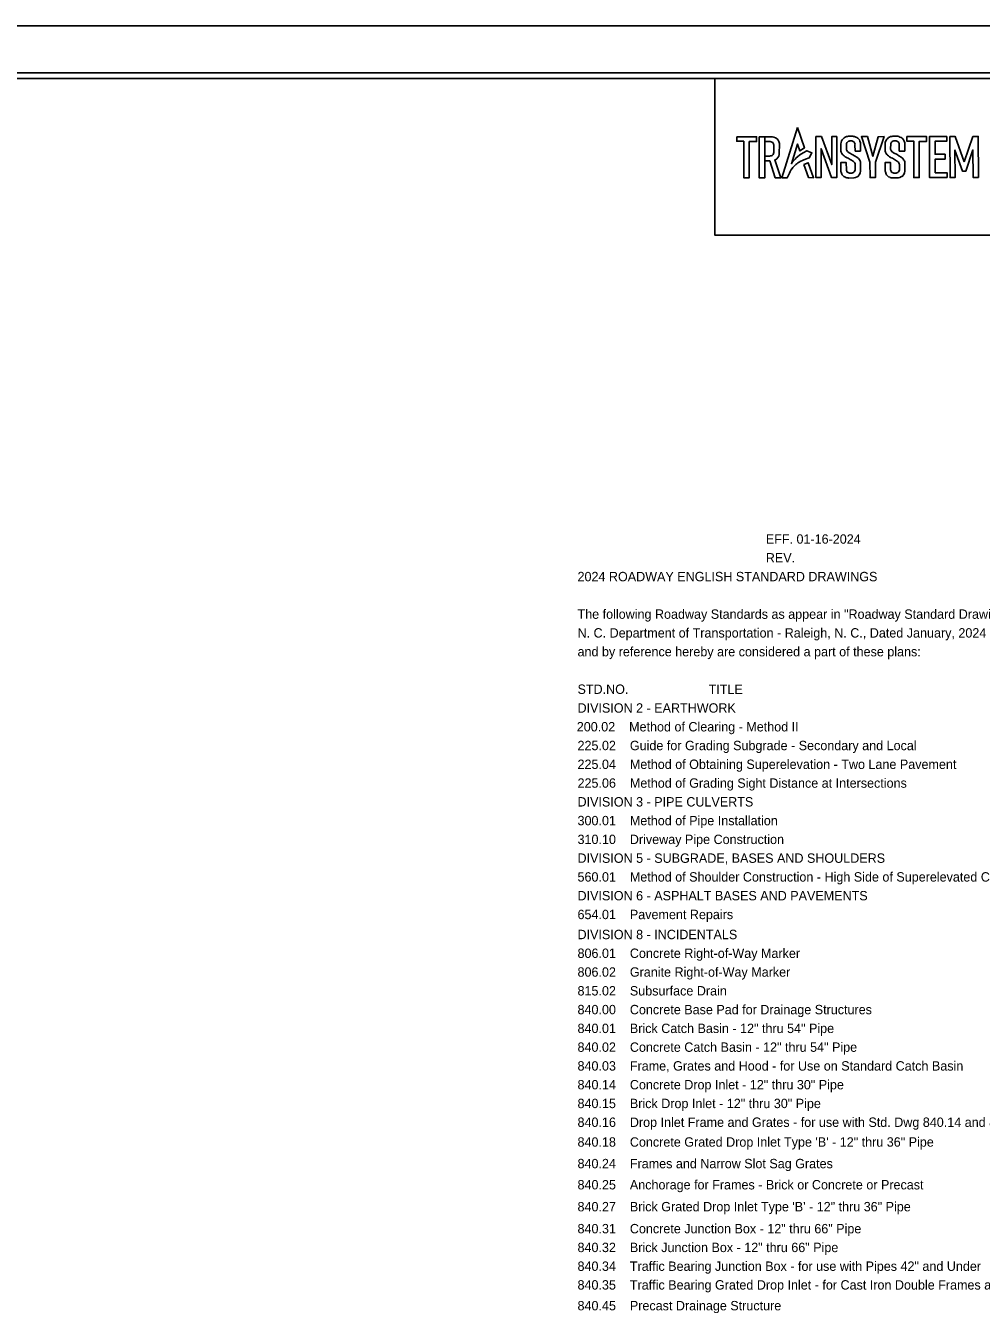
# Model space of a CAD drawing. Extents: x 1537922 to 1539606, y 409903 to 410998.
# Drawn here: x 1538895 to 1539302, y 410448 to 410998 of the extents above; entities that cross this region are included whole.
import ezdxf

# ---------------------------------------------------------------- set-up
doc = ezdxf.new("R2010")
doc.units = 0
for name, color, linetype in [('Default', 7, 'Continuous'), ('Old_Level_58', 7, 'Continuous'), ('Sheet Cutting Line CELL', 7, 'Continuous'), ('Sheet Plan CELL', 7, 'Continuous'), ('Sheet Plot Border Inside CELL', 7, 'Continuous'), ('Sheet Plot Border Outside CELL', 7, 'Continuous')]:
    doc.layers.add(name, color=color, linetype=linetype)

msp = doc.modelspace()

# ---------------------------------------------------------------- linework, layer by layer
at = {"layer": 'Default'}
for points in [[(1539224.12, 410954.94), (1539217.45, 410933.6), (1539219.67, 410933.61), (1539220.02, 410934.45), (1539220.59, 410935.61), (1539220.9, 410936.24), (1539221.28, 410936.78), (1539221.8, 410937.54), (1539222.13, 410938.01), (1539222.51, 410938.4), (1539222.89, 410938.79), (1539223.37, 410939.29), (1539223.78, 410939.56), (1539224.2, 410939.89), (1539224.76, 410940.21), (1539225.25, 410940.49), (1539226.47, 410941.06), (1539227.47, 410941.47), (1539229.11, 410942.03), (1539230.24, 410944.17), (1539228.07, 410945.13), (1539226.44, 410944.24), (1539225.06, 410943.34), (1539224.08, 410942.54), (1539223.55, 410942.11), (1539223.02, 410941.55), (1539222.49, 410940.98), (1539222.09, 410940.56), (1539221.71, 410939.91), (1539221.5, 410939.55), (1539224.13, 410947.93), (1539225.13, 410945.04), (1539227.03, 410946.29)], [(1539198.15, 410951.09), (1539206.62, 410951.1), (1539206.62, 410949.02), (1539203.51, 410949.02), (1539203.53, 410933.6), (1539201.18, 410933.6), (1539201.16, 410949.12), (1539198.19, 410949.12)], [(1539207.77, 410951.08), (1539210.09, 410951.09), (1539210.11, 410933.52), (1539207.79, 410933.52)], [(1539210.09, 410949), (1539212.48, 410949), (1539212.78, 410948.95), (1539213.18, 410948.79), (1539213.51, 410948.57), (1539213.74, 410948.3), (1539213.89, 410947.97), (1539214.02, 410947.71), (1539214.02, 410947.13), (1539214.03, 410944.64), (1539213.97, 410944.31), (1539213.88, 410943.87), (1539213.75, 410943.57), (1539213.55, 410943.31), (1539213.28, 410943.1), (1539212.86, 410942.95), (1539212.53, 410942.9), (1539212.2, 410942.86), (1539210.1, 410942.85), (1539210.11, 410940.74), (1539212.22, 410940.76), (1539214.59, 410933.59), (1539217, 410933.62), (1539214.35, 410941.16), (1539214.73, 410941.29), (1539215.27, 410941.69), (1539215.75, 410942.22), (1539216.1, 410942.86), (1539216.32, 410943.49), (1539216.3, 410943.68), (1539216.34, 410948.24), (1539216.14, 410948.99), (1539215.78, 410949.67), (1539215.37, 410950.14), (1539214.67, 410950.61), (1539213.99, 410950.84), (1539213.31, 410951.06), (1539212.91, 410951.06), (1539210.09, 410951.09)], [(1539231.89, 410951.12), (1539231.9, 410933.66), (1539234.14, 410933.66), (1539234.13, 410945.94), (1539238.58, 410933.64), (1539240.83, 410933.67), (1539240.81, 410951.17), (1539238.63, 410951.17), (1539238.65, 410939.19), (1539234.24, 410951.13)], [(1539248.58, 410944.95), (1539250.9, 410944.95), (1539250.89, 410948.43), (1539250.7, 410949.13), (1539250.42, 410949.72), (1539250.12, 410950.11), (1539249.75, 410950.46), (1539249.31, 410950.75), (1539248.88, 410950.92), (1539248.88, 410950.92), (1539248.42, 410951.12), (1539247.94, 410951.24), (1539247.62, 410951.32), (1539245.87, 410951.28), (1539245.34, 410951.19), (1539244.88, 410951.11), (1539244.42, 410950.87), (1539244.02, 410950.66), (1539243.62, 410950.38), (1539243.32, 410950.06), (1539243.07, 410949.7), (1539242.88, 410949.3), (1539242.62, 410948.61), (1539242.57, 410948.09), (1539242.57, 410944.92), (1539242.69, 410944.45), (1539242.92, 410943.95), (1539243.21, 410943.54), (1539243.5, 410943.23), (1539243.95, 410942.88), (1539244.41, 410942.54), (1539244.69, 410942.32), (1539245.17, 410942.09), (1539245.66, 410941.87), (1539246.05, 410941.61), (1539246.49, 410941.33), (1539247.02, 410941.06), (1539247.45, 410940.84), (1539247.88, 410940.53), (1539248.19, 410940.23), (1539248.44, 410939.99), (1539248.59, 410939.51), (1539248.69, 410939.21), (1539248.65, 410936.98), (1539248.49, 410936.49), (1539248.24, 410936.07), (1539247.92, 410935.78), (1539247.56, 410935.62), (1539247.22, 410935.55), (1539246.26, 410935.53), (1539245.94, 410935.62), (1539245.61, 410935.81), (1539245.28, 410936.01), (1539245.14, 410936.34), (1539244.99, 410936.68), (1539244.88, 410936.94), (1539244.84, 410940.06), (1539242.51, 410940.03), (1539242.55, 410936.32), (1539242.67, 410936.04), (1539242.94, 410935.17), (1539243.11, 410934.88), (1539243.37, 410934.56), (1539243.75, 410934.19), (1539244.05, 410934), (1539244.49, 410933.81), (1539244.64, 410933.75), (1539245.07, 410933.56), (1539245.61, 410933.51), (1539246, 410933.47), (1539248.14, 410933.53), (1539248.74, 410933.67), (1539249.56, 410934.04), (1539249.84, 410934.17), (1539250.46, 410934.96), (1539250.8, 410935.75), (1539250.95, 410936.46), (1539250.9, 410939.88), (1539250.89, 410940.35), (1539250.76, 410940.73), (1539250.57, 410941.08), (1539250.03, 410941.84), (1539249.32, 410942.4), (1539248.35, 410942.98), (1539247.6, 410943.42), (1539246.14, 410944.19), (1539245.39, 410944.75), (1539245.06, 410945.17), (1539244.98, 410945.45), (1539244.9, 410945.74), (1539244.95, 410948.17), (1539245.07, 410948.42), (1539245.2, 410948.68), (1539245.37, 410948.83), (1539245.61, 410949.03), (1539245.86, 410949.13), (1539246.12, 410949.24), (1539246.27, 410949.21), (1539246.29, 410949.29), (1539247.24, 410949.27), (1539247.52, 410949.16), (1539247.8, 410949.05), (1539248.08, 410948.94), (1539248.21, 410948.75), (1539248.39, 410948.47), (1539248.48, 410948.19), (1539248.58, 410947.92), (1539248.57, 410947.61)], [(1539253.86, 410951.13), (1539251.32, 410951.13), (1539254.94, 410940.25), (1539254.97, 410933.7), (1539257.36, 410933.71), (1539257.33, 410940.21), (1539260.98, 410951.17), (1539258.49, 410951.1), (1539256.18, 410942.76)], [(1539267.46, 410944.97), (1539269.77, 410944.97), (1539269.76, 410948.45), (1539269.57, 410949.15), (1539269.29, 410949.74), (1539268.99, 410950.13), (1539268.62, 410950.48), (1539268.18, 410950.77), (1539267.75, 410950.94), (1539267.75, 410950.94), (1539267.3, 410951.13), (1539266.81, 410951.25), (1539266.49, 410951.34), (1539264.74, 410951.3), (1539264.21, 410951.21), (1539263.76, 410951.13), (1539263.3, 410950.89), (1539262.89, 410950.68), (1539262.5, 410950.39), (1539262.19, 410950.08), (1539261.94, 410949.72), (1539261.75, 410949.32), (1539261.5, 410948.62), (1539261.44, 410948.11), (1539261.45, 410944.94), (1539261.56, 410944.46), (1539261.79, 410943.97), (1539262.08, 410943.56), (1539262.37, 410943.25), (1539262.83, 410942.9), (1539263.28, 410942.55), (1539263.56, 410942.33), (1539264.05, 410942.11), (1539264.53, 410941.88), (1539264.92, 410941.63), (1539265.36, 410941.34), (1539265.89, 410941.08), (1539266.32, 410940.86), (1539266.75, 410940.54), (1539267.06, 410940.25), (1539267.31, 410940.01), (1539267.46, 410939.53), (1539267.56, 410939.23), (1539267.52, 410936.99), (1539267.36, 410936.51), (1539267.12, 410936.09), (1539266.79, 410935.8), (1539266.43, 410935.64), (1539266.09, 410935.57), (1539265.13, 410935.55), (1539264.81, 410935.64), (1539264.48, 410935.83), (1539264.15, 410936.02), (1539264.01, 410936.36), (1539263.87, 410936.69), (1539263.75, 410936.96), (1539263.72, 410940.07), (1539261.38, 410940.05), (1539261.42, 410936.34), (1539261.54, 410936.05), (1539261.81, 410935.19), (1539261.99, 410934.9), (1539262.24, 410934.58), (1539262.62, 410934.21), (1539262.92, 410934.01), (1539263.36, 410933.83), (1539263.52, 410933.76), (1539263.95, 410933.58), (1539264.48, 410933.53), (1539264.87, 410933.49), (1539267.02, 410933.54), (1539267.61, 410933.69), (1539268.44, 410934.06), (1539268.71, 410934.19), (1539269.34, 410934.98), (1539269.67, 410935.76), (1539269.83, 410936.47), (1539269.77, 410939.9), (1539269.76, 410940.37), (1539269.63, 410940.74), (1539269.44, 410941.1), (1539268.9, 410941.86), (1539268.19, 410942.41), (1539267.22, 410942.99), (1539266.48, 410943.44), (1539265.01, 410944.2), (1539264.26, 410944.76), (1539263.93, 410945.19), (1539263.85, 410945.47), (1539263.77, 410945.75), (1539263.82, 410948.19), (1539263.94, 410948.44), (1539264.07, 410948.7), (1539264.25, 410948.85), (1539264.48, 410949.04), (1539264.74, 410949.15), (1539265, 410949.26), (1539265.14, 410949.23), (1539265.16, 410949.3), (1539266.12, 410949.29), (1539266.39, 410949.18), (1539266.67, 410949.07), (1539266.95, 410948.96), (1539267.08, 410948.77), (1539267.26, 410948.49), (1539267.36, 410948.21), (1539267.45, 410947.94), (1539267.44, 410947.63)], [(1539270.61, 410951.16), (1539279.08, 410951.16), (1539279.08, 410949.09), (1539275.97, 410949.09), (1539275.99, 410933.66), (1539273.64, 410933.66), (1539273.62, 410949.19), (1539270.65, 410949.19)], [(1539287.69, 410951.16), (1539280.3, 410951.15), (1539280.32, 410933.73), (1539287.79, 410933.74), (1539287.79, 410935.71), (1539282.74, 410935.7), (1539282.74, 410941.55), (1539286.95, 410941.55), (1539286.95, 410943.62), (1539282.7, 410943.62), (1539282.69, 410949.12), (1539287.71, 410949.12)], [(1539295.06, 410940.31), (1539291.25, 410951.23), (1539289.04, 410951.13), (1539289.12, 410933.67), (1539291.23, 410933.68), (1539291.17, 410945.36), (1539294.44, 410936.37), (1539295.79, 410936.34), (1539298.86, 410945.47), (1539298.9, 410933.75), (1539301.18, 410933.75), (1539301.12, 410951.18), (1539298.82, 410951.17)], [(1539226.73, 410939.23), (1539228.65, 410940), (1539230.91, 410933.56), (1539228.81, 410933.64)]]:
    msp.add_lwpolyline(points, close=True, dxfattribs=at)
at = {"layer": 'Old_Level_58'}
msp.add_lwpolyline([(1539188.77, 410975.85), (1539388.82, 410975.85), (1539388.82, 410909.16), (1539188.77, 410909.16)], close=True, dxfattribs=at)
at = {"layer": 'Sheet Cutting Line CELL'}
msp.add_line((1539605.87, 410998.35), (1537922.37, 410998.35), dxfattribs=at)
at = {"layer": 'Sheet Plan CELL'}
msp.add_lwpolyline([(1539588.87, 410975.85), (1538088.87, 410975.85), (1538088.87, 409925.85), (1539588.87, 409925.85)], close=True, dxfattribs=at)
at = {"layer": 'Sheet Plot Border Inside CELL'}
msp.add_lwpolyline([(1537935.37, 409923.35), (1539601.37, 409923.35), (1539601.37, 410978.35), (1537935.37, 410978.35)], close=True, dxfattribs=at)
at = {"layer": 'Sheet Plot Border Outside CELL'}
msp.add_lwpolyline([(1537922.37, 409903.35), (1539605.87, 409903.35), (1539605.87, 410998.35), (1537922.37, 410998.35)], close=True, dxfattribs=at)

# ---------------------------------------------------------------- texts
at = {"layer": 'Default'}
for s, p in [('                                                      EFF. 01-16-2024', (1539130.32, 410777.62)), ('                                                      REV. ', (1539130.32, 410769.62)), ('2024 ROADWAY ENGLISH STANDARD DRAWINGS', (1539130.32, 410761.62)), ('The following Roadway Standards as appear in "Roadway Standard Drawings" Highway Design Branch -', (1539130.32, 410745.62)), ('N. C. Department of Transportation - Raleigh, N. C., Dated January, 2024 are applicable to this project', (1539130.32, 410737.62)), ('and by reference hereby are considered a part of these plans:', (1539130.32, 410729.62)), ('STD.NO.                       TITLE', (1539130.32, 410713.62)), ('DIVISION 2 - EARTHWORK', (1539130.32, 410705.62)), ('200.02    Method of Clearing - Method II', (1539130, 410697.62)), ('225.02    Guide for Grading Subgrade - Secondary and Local', (1539130.32, 410689.62)), ('225.04    Method of Obtaining Superelevation - Two Lane Pavement', (1539130.32, 410681.62)), ('225.06    Method of Grading Sight Distance at Intersections', (1539130.32, 410673.62)), ('DIVISION 3 - PIPE CULVERTS', (1539130.32, 410665.62)), ('300.01    Method of Pipe Installation ', (1539130.32, 410657.62)), ('310.10    Driveway Pipe Construction', (1539130.32, 410649.62)), ('DIVISION 5 - SUBGRADE, BASES AND SHOULDERS', (1539130.32, 410641.62)), ('560.01    Method of Shoulder Construction - High Side of Superelevated Curve - Method I', (1539130.32, 410633.62)), ('DIVISION 6 - ASPHALT BASES AND PAVEMENTS', (1539130.32, 410625.62)), ('654.01    Pavement Repairs', (1539130.32, 410617.62)), ('DIVISION 8 - INCIDENTALS', (1539130.32, 410609.08)), ('806.01    Concrete Right-of-Way Marker', (1539130.32, 410601.08)), ('806.02    Granite Right-of-Way Marker', (1539130.32, 410593.08)), ('815.02    Subsurface Drain', (1539130.32, 410585.08)), ('840.00    Concrete Base Pad for Drainage Structures', (1539130.32, 410577.07)), ('840.01    Brick Catch Basin - 12" thru 54" Pipe', (1539130.32, 410569.07)), ('840.02    Concrete Catch Basin - 12" thru 54" Pipe', (1539130.32, 410561.07)), ('840.03    Frame, Grates and Hood - for Use on Standard Catch Basin', (1539130.32, 410553.07)), ('840.14    Concrete Drop Inlet - 12" thru 30" Pipe', (1539130.32, 410545.07)), ('840.15    Brick Drop Inlet - 12" thru 30" Pipe', (1539130.32, 410537.07)), ('840.16    Drop Inlet Frame and Grates - for use with Std. Dwg 840.14 and 840.15', (1539130.32, 410529.07)), ('840.18    Concrete Grated Drop Inlet Type \'B\' - 12" thru 36" Pipe', (1539130.32, 410520.64)), ('840.24    Frames and Narrow Slot Sag Grates', (1539130.32, 410511.44)), ('840.25    Anchorage for Frames - Brick or Concrete or Precast', (1539130.32, 410502.43)), ('840.27    Brick Grated Drop Inlet Type \'B\' - 12" thru 36" Pipe', (1539130.32, 410493.08)), ('840.31    Concrete Junction Box - 12" thru 66" Pipe', (1539130.32, 410483.71)), ('840.32    Brick Junction Box - 12" thru 66" Pipe', (1539130.32, 410475.71)), ('840.34    Traffic Bearing Junction Box - for use with Pipes 42" and Under', (1539130.32, 410467.71)), ('840.35    Traffic Bearing Grated Drop Inlet - for Cast Iron Double Frames and Grates', (1539130.32, 410459.74)), ('840.45    Precast Drainage Structure', (1539130.32, 410450.89))]:
    msp.add_text(s, height=4, dxfattribs=at).set_placement(p)

doc.saveas('drawing.dxf')
